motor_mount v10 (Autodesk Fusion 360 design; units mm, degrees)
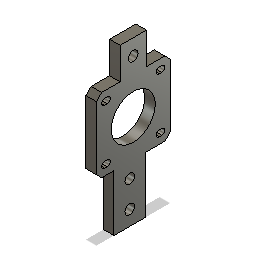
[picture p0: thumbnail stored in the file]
sketch "Sketch1" plane through (0, 0, 0) normal (1, 0, 0) x axis (0, 0, -1)
  line L1 (21, 21) -> (-21, 21)
  line L2 (21, -21) -> (21, 21)
  line L3 (-21, -21) -> (21, -21)
  line L4 (-21, 21) -> (-21, -21)
  line L5 (7, -21) -> (-11, -21)
  line L6 (-11, -53) -> (7, -53)
  line L7 (-11, -21) -> (-11, -53)
  line L8 (21, 0) -> (-21, 0)
  line L9 (-2, -29.5) -> (-2, -44.5)
  line L10 (-14.75, 17.2) -> (-16.25, 17.2)
  line L11 (-16.25, 13.8) -> (-14.75, 13.8)
  line L12 (-16.25, 15.5) -> (-14.75, 15.5)
  line L13 (0, 2.5) -> (0, 20)
  line L14 (16.25, 13.8) -> (14.75, 13.8)
  line L15 (14.75, 17.2) -> (16.25, 17.2)
  line L16 (-16.25, -13.8) -> (-14.75, -13.8)
  line L17 (-14.75, -17.2) -> (-16.25, -17.2)
  line L18 (14.75, -17.2) -> (16.25, -17.2)
  line L19 (16.25, -13.8) -> (14.75, -13.8)
  line L20 (7, -21) -> (7, -53)
  circle C1 centre (0, 0) radius 12.5
  circle C2 centre (-2, -29.5) radius 2.75
  circle C3 centre (-2, -44.5) radius 2.75
  arc A1 centre (-14.75, 15.5) radius 1.7 clockwise from (-14.75, 17.2) to (-14.75, 13.8)
  arc A2 centre (-16.25, 15.5) radius 1.7 clockwise from (-16.25, 13.8) to (-16.25, 17.2)
  arc A3 centre (16.25, 15.5) radius 1.7 clockwise from (16.25, 17.2) to (16.25, 13.8)
  arc A4 centre (14.75, 15.5) radius 1.7 clockwise from (14.75, 13.8) to (14.75, 17.2)
  arc A5 centre (-14.75, -15.5) radius 1.7 clockwise from (-14.75, -13.8) to (-14.75, -17.2)
  arc A6 centre (-16.25, -15.5) radius 1.7 clockwise from (-16.25, -17.2) to (-16.25, -13.8)
  arc A7 centre (14.75, -15.5) radius 1.7 clockwise from (14.75, -17.2) to (14.75, -13.8)
  arc A8 centre (16.25, -15.5) radius 1.7 clockwise from (16.25, -13.8) to (16.25, -17.2)
  point P9 (-21, 0)
  point P10 (21, 0)
  point P11 (0, 0)
  point P1 (0, 0)
  point P14 (-2, -53)
  point P13 (-2, -44.5)
  point P15 (-2, -44.5)
  point P12 (-2, -29.5)
  point P16 (-2, -29.5)
  point P17 (-2, -37)
  point P18 (-16.25, 17.2)
  point P23 (-16.25, 17.2)
  point P21 (-14.75, 15.5)
  point P25 (-14.75, 15.5)
  point P24 (-16.25, 15.5)
  point P26 (-16.25, 15.5)
  point P27 (-15.5, 15.5)
  point P34 (16.25, 17.2)
  point P19 (-14.75, 17.2)
  point P35 (14.75, 17.2)
  point P20 (-14.75, 13.8)
  point P30 (14.75, 13.8)
  point P22 (-16.25, 13.8)
  point P31 (16.25, 13.8)
  point P33 (16.25, 17.2)
  point P43 (-16.25, -17.2)
  point P39 (-14.75, -17.2)
  point P38 (-14.75, -13.8)
  point P40 (-16.25, -13.8)
  point P42 (-16.25, -17.2)
  point P46 (14.75, -13.8)
  point P49 (16.25, -13.8)
  point P50 (16.25, -17.2)
  point P47 (16.25, -17.2)
  point P45 (14.75, -17.2)
  point P4 (21, -21)
  point P52 (21, -21)
  point P51 (7, -21)
  point P2 (-21, 21)
  point P3 (21, 21)
  point P7 (7, -53)
  point P8 (-11, -53)
  horizontal L1
  vertical L2
  horizontal L3
  vertical L4
  horizontal L5
  horizontal L6
  vertical L7
  midpoint L4 P9
  midpoint L2 P10
  midpoint L8 P11
  coincident P1 P11
  midpoint L6 P14
  coincident P13 P15
  coincident P12 P16
  midpoint L9 P17
  tangent L10 A1
  tangent L11 A2
  horizontal L10
  tangent A1 L11
  horizontal L11
  coincident P18 P23
  tangent L10 A2
  coincident P21 P25
  coincident P24 P26
  midpoint L12 P27
  symmetric P18 L13 P34
  symmetric P19 L13 P35
  symmetric P20 L13 P30
  symmetric A1 L13 A4
  symmetric P22 L13 P31
  symmetric P23 L13 P33
  symmetric A2 L13 A3
  symmetric L8 P18 P43
  symmetric L8 P19 P39
  symmetric L8 P20 P38
  symmetric L8 A1 A5
  symmetric L8 P22 P40
  symmetric L8 P23 P42
  symmetric L8 A2 A6
  symmetric L8 P30 P46
  symmetric L8 P31 P49
  symmetric L8 P33 P50
  symmetric L8 A3 A8
  symmetric L8 P34 P47
  symmetric L8 P35 P45
  symmetric L8 A4 A7
  vertical L20
  coincident P4 P52
  coincident L3 P51
  vertical L9
  vertical P14 P17
  dimension "d1" distance P2 P3 = 42
  dimension "d4" distance P3 P4 = 42
  dimension "d8" diameter C1 = 25
  dimension "d9" diameter C2 = 5.5
  dimension "d12" diameter C3 = 5.5
  dimension "d13" distance P12 P13 = 15
  dimension "d28" distance P25 P26 = 1.5
  dimension "d29" distance P1 P27 = 15.5
  dimension "d30" distance P11 P27 = 15.5
  dimension "d31" radius A1 = 1.7 (= "3.4 mm / 2")
  dimension "d32" distance P7 P51 = 32
  dimension "d33" distance P7 P8 = 18
  dimension "d34" distance P4 P17 = 16
  dimension "d35" distance P1 P17 = 2
extrude "Extrude1" new body sketch "Sketch1" profile of L1 L2 L3 L4 L5 L6 L7 C1 C2 C3 L10 A1 L11 A2 L14 A3 L15 A4 A5 L16 A6 L17 A7 L18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 along normal blind 6
sketch "Sketch4" plane through (0, 0, 0) normal (-1, 0, 0) x axis (0, 0, 1)
  line L1 (21, 21) -> (21, -21)
  line L2 (-21, 21) -> (21, 21)
  line L3 (7.5, 21) -> (-7.5, 21)
  line L4 (7.5, 39) -> (7.5, 21)
  line L5 (-7.5, 39) -> (7.5, 39)
  line L6 (-7.5, 21) -> (-7.5, 39)
  line L7 (-21, -21) -> (-21, 21)
  line L8 (-7, -21) -> (-21, -21)
  line L9 (11, -53) -> (-7, -53)
  line L10 (11, -21) -> (11, -53)
  line L11 (21, -21) -> (11, -21)
  line L12 (-7, -53) -> (-7, -21)
  line L13 (-16.25, 13.8) -> (-14.75, 13.8)
  line L14 (-14.75, 17.2) -> (-16.25, 17.2)
  line L15 (14.75, -17.2) -> (16.25, -17.2)
  line L16 (16.25, -13.8) -> (14.75, -13.8)
  line L17 (-14.75, -13.8) -> (-16.25, -13.8)
  line L18 (-16.25, -17.2) -> (-14.75, -17.2)
  line L19 (16.25, 17.2) -> (14.75, 17.2)
  line L20 (14.75, 13.8) -> (16.25, 13.8)
  circle C1 centre (0, 0) radius 12.5
  circle C2 centre (2, -44.5) radius 2.75
  circle C3 centre (2, -29.5) radius 2.75
  arc A1 centre (-14.75, 15.5) radius 1.7 clockwise from (-14.75, 17.2) to (-14.75, 13.8)
  arc A2 centre (-16.25, 15.5) radius 1.7 clockwise from (-16.25, 13.8) to (-16.25, 17.2)
  arc A3 centre (14.75, -15.5) radius 1.7 clockwise from (14.75, -17.2) to (14.75, -13.8)
  arc A4 centre (16.25, -15.5) radius 1.7 clockwise from (16.25, -13.8) to (16.25, -17.2)
  arc A5 centre (-16.25, -15.5) radius 1.7 clockwise from (-16.25, -17.2) to (-16.25, -13.8)
  arc A6 centre (-14.75, -15.5) radius 1.7 clockwise from (-14.75, -13.8) to (-14.75, -17.2)
  arc A7 centre (14.75, 15.5) radius 1.7 clockwise from (14.75, 13.8) to (14.75, 17.2)
  arc A8 centre (16.25, 15.5) radius 1.7 clockwise from (16.25, 17.2) to (16.25, 13.8)
  point P6 (-7.5, 21)
  point P10 (0, 21)
  point P1 (0, 0)
  point P9 (-7.5, 39)
  point P8 (7.5, 39)
  horizontal L3
  vertical L4
  horizontal L5
  vertical L6
  coincident L2 P6
  midpoint L3 P10
  vertical P1 P10
  dimension "d18" distance P6 P9 = 18
  dimension "d19" distance P8 P9 = 15
extrude "Extrude2" add sketch "Sketch4" profile of L2 L3 L4 L5 L6 to an object
sketch "Sketch5" plane through (0, 0, 0) normal (-1, 0, 0) x axis (0, 0, 1)
  line L1 (21, 21) -> (21, -21)
  line L2 (7.5, 21) -> (21, 21)
  line L3 (7.5, 39) -> (7.5, 21)
  line L4 (-7.5, 39) -> (7.5, 39)
  line L5 (-7.5, 21) -> (-7.5, 39)
  line L6 (-21, 21) -> (-7.5, 21)
  line L7 (-21, -21) -> (-21, 21)
  line L8 (-7, -21) -> (-21, -21)
  line L9 (11, -53) -> (-7, -53)
  line L10 (11, -21) -> (11, -53)
  line L11 (21, -21) -> (11, -21)
  line L12 (-7, -53) -> (-7, -21)
  line L13 (-16.25, 13.8) -> (-14.75, 13.8)
  line L14 (-14.75, 17.2) -> (-16.25, 17.2)
  line L15 (14.75, -17.2) -> (16.25, -17.2)
  line L16 (16.25, -13.8) -> (14.75, -13.8)
  line L17 (-14.75, -13.8) -> (-16.25, -13.8)
  line L18 (-16.25, -17.2) -> (-14.75, -17.2)
  line L19 (16.25, 17.2) -> (14.75, 17.2)
  line L20 (14.75, 13.8) -> (16.25, 13.8)
  circle C1 centre (0, 0) radius 12.5
  circle C2 centre (0, 30) radius 2.75
  circle C3 centre (2, -44.5) radius 2.75
  circle C4 centre (2, -29.5) radius 2.75
  arc A1 centre (-14.75, 15.5) radius 1.7 clockwise from (-14.75, 17.2) to (-14.75, 13.8)
  arc A2 centre (-16.25, 15.5) radius 1.7 clockwise from (-16.25, 13.8) to (-16.25, 17.2)
  arc A3 centre (14.75, -15.5) radius 1.7 clockwise from (14.75, -17.2) to (14.75, -13.8)
  arc A4 centre (16.25, -15.5) radius 1.7 clockwise from (16.25, -13.8) to (16.25, -17.2)
  arc A5 centre (-16.25, -15.5) radius 1.7 clockwise from (-16.25, -17.2) to (-16.25, -13.8)
  arc A6 centre (-14.75, -15.5) radius 1.7 clockwise from (-14.75, -13.8) to (-14.75, -17.2)
  arc A7 centre (14.75, 15.5) radius 1.7 clockwise from (14.75, 13.8) to (14.75, 17.2)
  arc A8 centre (16.25, 15.5) radius 1.7 clockwise from (16.25, 17.2) to (16.25, 13.8)
  point P1 (0, 0)
  point P10 (0, 30)
  vertical P1 P10
  dimension "d22" distance P1 P10 = 30
  dimension "d23" diameter C2 = 5.5
extrude "Extrude3" cut sketch "Sketch5" profile of C2 against normal blind 30
chamfer "Chamfer1" distance 3
sketch "Sketch6" plane through (6, 0, 0) normal (1, 0, 0) x axis (0, 0, -1)
  line L1 (7.5, 21) -> (18, 21)
  line L2 (7.5, 39) -> (7.5, 21)
  line L3 (-7.5, 39) -> (7.5, 39)
  line L4 (-7.5, 21) -> (-7.5, 39)
  line L5 (-18, 21) -> (-7.5, 21)
  line L6 (-21, 18) -> (-18, 21)
  line L7 (-21, -18) -> (-21, 18)
  line L8 (18, -21) -> (7, -21)
  line L9 (21, 18) -> (21, -18)
  line L10 (-18, -21) -> (-21, -18)
  line L11 (-11, -21) -> (-18, -21)
  line L12 (-11, -53) -> (-11, -21)
  line L13 (7, -53) -> (-11, -53)
  line L14 (7, -21) -> (7, -53)
  line L15 (18, 21) -> (21, 18)
  line L16 (21, -18) -> (18, -21)
  line L17 (16.25, 17.2) -> (14.75, 17.2)
  line L18 (14.75, 13.8) -> (16.25, 13.8)
  line L19 (-16.25, -17.2) -> (-14.75, -17.2)
  line L20 (-14.75, -13.8) -> (-16.25, -13.8)
  line L21 (14.75, -17.2) -> (16.25, -17.2)
  line L22 (16.25, -13.8) -> (14.75, -13.8)
  line L23 (-16.25, 13.8) -> (-14.75, 13.8)
  line L24 (-14.75, 17.2) -> (-16.25, 17.2)
  circle C1 centre (0, 0) radius 12.5
  circle C2 centre (0, 30) radius 2.75
  circle C3 centre (-2, -44.5) radius 2.75
  circle C4 centre (-2, -29.5) radius 2.75
  arc A1 centre (14.75, 15.5) radius 1.7 clockwise from (14.75, 13.8) to (14.75, 17.2)
  arc A2 centre (16.25, 15.5) radius 1.7 clockwise from (16.25, 17.2) to (16.25, 13.8)
  arc A3 centre (-16.25, -15.5) radius 1.7 clockwise from (-16.25, -17.2) to (-16.25, -13.8)
  arc A4 centre (-14.75, -15.5) radius 1.7 clockwise from (-14.75, -13.8) to (-14.75, -17.2)
  arc A5 centre (16.25, -15.5) radius 1.7 clockwise from (16.25, -13.8) to (16.25, -17.2)
  arc A6 centre (14.75, -15.5) radius 1.7 clockwise from (14.75, -17.2) to (14.75, -13.8)
  arc A7 centre (-14.75, 15.5) radius 1.7 clockwise from (-14.75, 17.2) to (-14.75, 13.8)
  arc A8 centre (-16.25, 15.5) radius 1.7 clockwise from (-16.25, 13.8) to (-16.25, 17.2)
